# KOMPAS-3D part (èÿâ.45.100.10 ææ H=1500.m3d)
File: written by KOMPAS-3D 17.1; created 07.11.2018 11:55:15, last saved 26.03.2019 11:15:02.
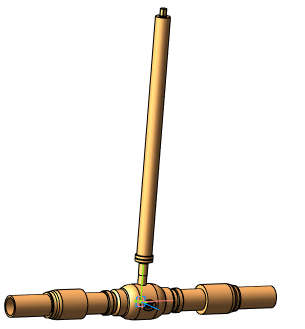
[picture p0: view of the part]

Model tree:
1. Операция без истории:2  (labels: Сталь 20  ГОСТ 1050-2013)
